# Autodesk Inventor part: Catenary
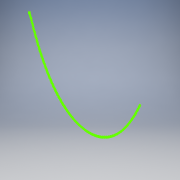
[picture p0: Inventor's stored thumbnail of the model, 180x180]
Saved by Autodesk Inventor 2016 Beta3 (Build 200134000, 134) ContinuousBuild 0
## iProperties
Created: 2008-02
Part Number: Catenary
Document SubType Name: Modeling
Designer: Autodesk, Inc.
Density: 1 g/cm^3
Material: Generic
Appearance: Default
Author: Autodesk, Inc.
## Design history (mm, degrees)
sketch "Sketch1"
  geometry: 300 further points
  constraints: 300 other
